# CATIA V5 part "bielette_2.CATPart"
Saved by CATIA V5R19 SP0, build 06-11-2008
Part number: skl_bielette_2
Publications: "axe_pivot_bielette2_levier", "axe_pivot_bielette2_sabot1", "Plan.1"
Bounding box of the stored display mesh (mm): x 0 to 110, y 355 to 410, z -20 to 20
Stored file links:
  C:\Users\Thibaud\Desktop\IFMA\thinkmotion\IAO\modele_catia\squelette\bielette_2.CATPart
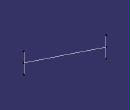
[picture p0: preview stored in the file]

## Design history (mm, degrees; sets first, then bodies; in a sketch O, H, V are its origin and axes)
Body1 (main body)
  Point1 "Point.2": stored without definition
  Point2: stored without definition
  Line1: type PtPt, SecondPoint Point2, FirstPoint Point1
  Plane1: stored without definition
  Point3 "Point.2": stored without definition
  Line2 "axe_pivot_bielette2_levier": type Normal, RefSkin Plane1, Start -20, End 20, RefPoint Point3
  Plane2: stored without definition
  Point4: stored without definition
  Line3 "axe_pivot_bielette2_sabot1": type Normal, RefSkin Plane2, Start -20, End 20, RefPoint Point4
